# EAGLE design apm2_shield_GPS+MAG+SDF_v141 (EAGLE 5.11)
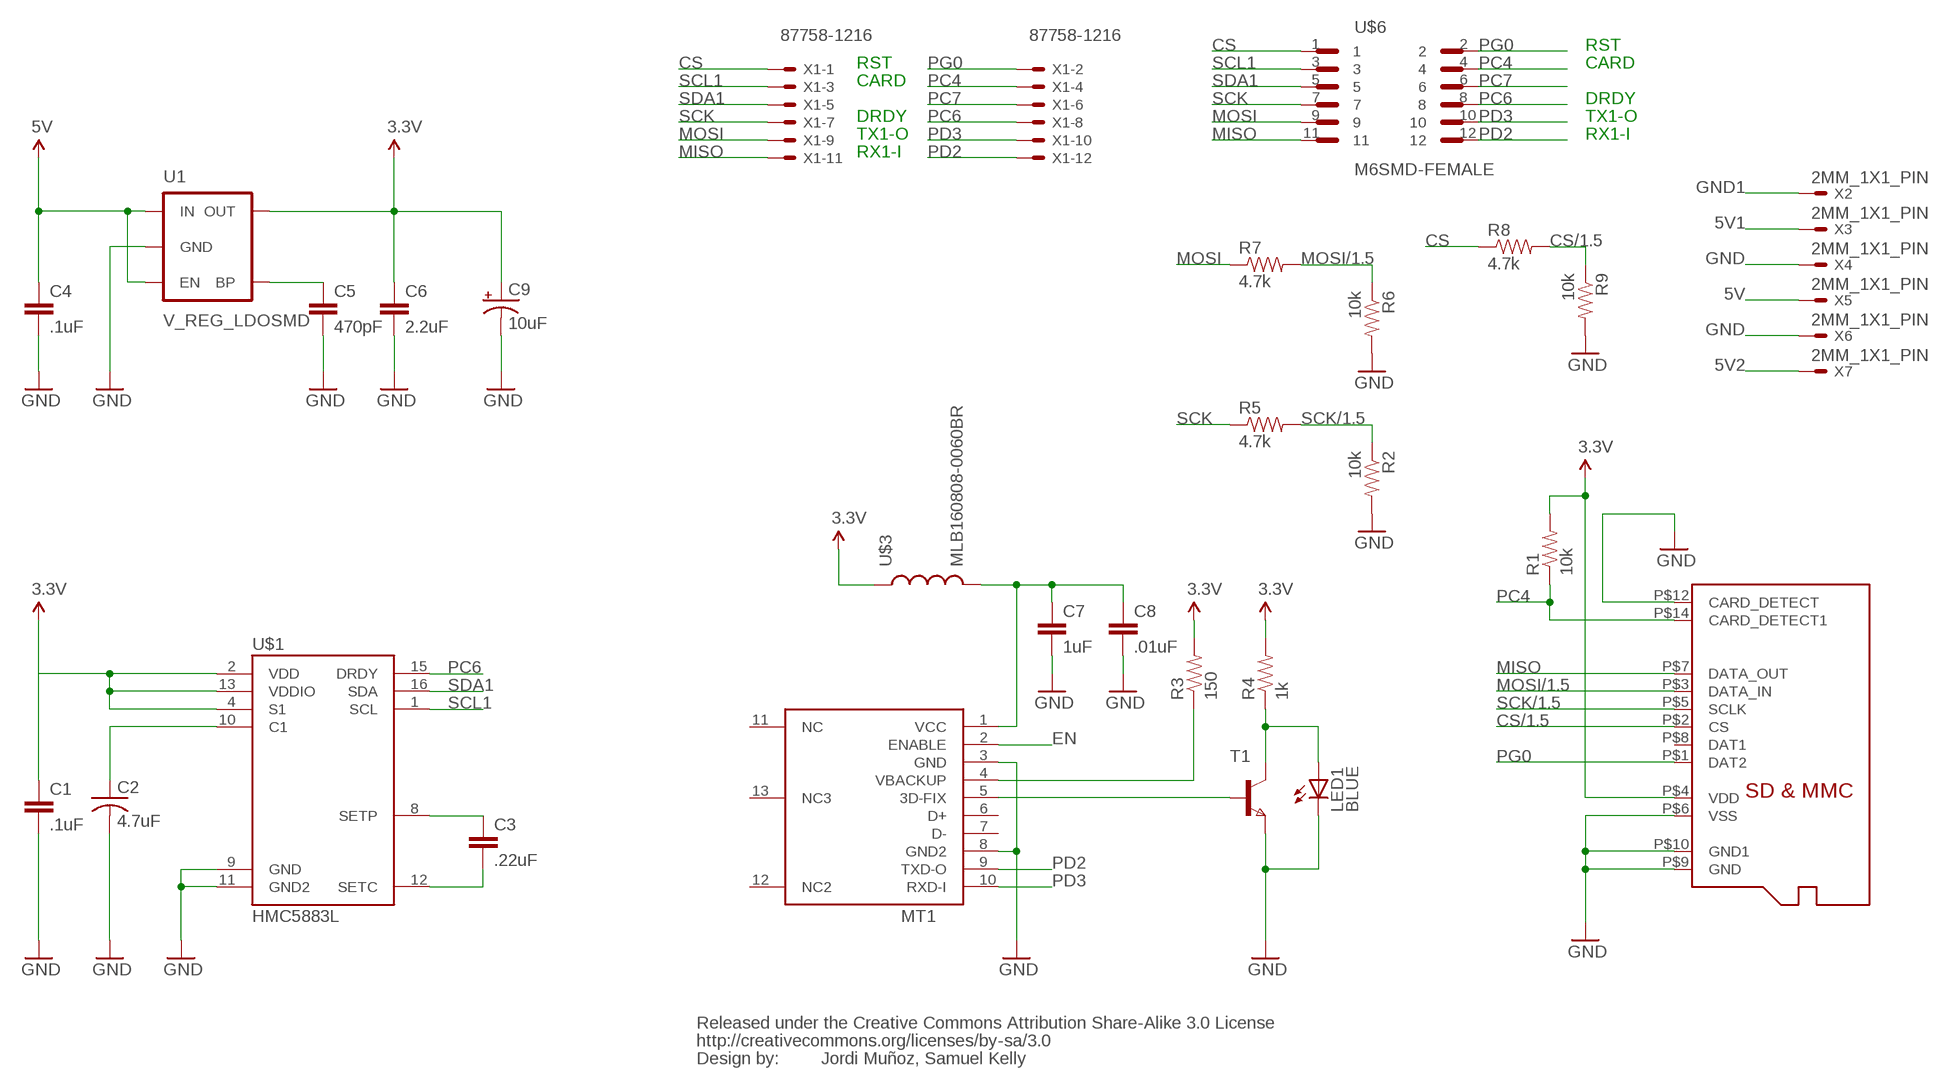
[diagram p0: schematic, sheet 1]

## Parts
C1  .1uF  CAP0402-CAP  [0402-CAP]
C2  4.7uF  C-USC1206  [C1206]
C3  .22uF  CAP0402-CAP  [0402-CAP]
C4  .1uF  CAP0402-CAP  [0402-CAP]
C5  470pF  CAP0402-CAP  [0402-CAP]
C6  2.2uF  CAP0402-CAP  [0402-CAP]
C7  1uF  CAP0402-CAP  [0402-CAP]
C8  .01uF  CAP0402-CAP  [0402-CAP]
C9  10uF  CAP_POL1206  [EIA3216]
LED1  BLUE  LED0603  [LED-0603]
MT1  MEDIATEK_MT3329_ANT_REV  [MEDIATEK_MT3329_ANT_REV]
R1  10k  RESISTOR0402-RES  [0402-RES]
R2  10k  RESISTOR0402-RES  [0402-RES]
R3  150  RESISTOR0402-RES  [0402-RES]
R4  1k  RESISTOR0402-RES  [0402-RES]
R5  4.7k  RESISTOR0402-RES  [0402-RES]
R6  10k  RESISTOR0402-RES  [0402-RES]
R7  4.7k  RESISTOR0402-RES  [0402-RES]
R8  4.7k  RESISTOR0402-RES  [0402-RES]
R9  10k  RESISTOR0402-RES  [0402-RES]
T1  NPNSOT323  [SOT323]
U1  V_REG_LDOSMD  [SOT23-5]
U$1  HMC5883L  [LPCC16]
U$3  MLB160808-0060BR  INDUCTOR0402  [C0402]
U$4  CREATIVE_COMMONS  [CREATIVE_COMMONS]
U$5  MICROSD'NON-PUSH'  [MICROSD_AMPHENOL]
U$6  M6SMD-FEMALE  [M6-2X6-2MM]
X1  87758-1216  [87758-1216]
X2  2MM_1X1_PIN  [2MM_1X1_PIN]
X3  2MM_1X1_PIN  [2MM_1X1_PIN]
X4  2MM_1X1_PIN  [2MM_1X1_PIN]
X5  2MM_1X1_PIN  [2MM_1X1_PIN]
X6  2MM_1X1_PIN  [2MM_1X1_PIN]
X7  2MM_1X1_PIN  [2MM_1X1_PIN]

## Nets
3.3V: C1.1 C6.1 C9.A(+) R1.2 R3.2 R4.2 U1.5(OUT) U$1.2(VDD) U$1.4(S1) U$1.13(VDDIO) U$3.1 U$5.P$4(VDD)
5V: C4.1 U1.1(IN) U1.3(EN) X5.P$1(S)
5V1: X3.P$1(S)
5V2: X7.P$1(S)
CS: R8.1 U$6.1 X1.1
CS/1.5: R8.2 R9.1 U$5.P$2(CS)
EN: MT1.2(ENABLE)
GND: C1.2 C2.2 C4.2 C5.2 C6.2 C7.2 C8.2 C9.C(-) LED1.C MT1.3(GND) MT1.8(GND2) R2.2 R6.2 R9.2 T1.3(E) U1.2(GND) U$1.9(GND) U$1.11(GND2) U$5.P$6(VSS) U$5.P$9(GND) U$5.P$10(GND1) U$5.P$12(CARD_DETECT) X4.P$1(S) X6.P$1(S)
GND1: X2.P$1(S)
MISO: U$5.P$7(DATA_OUT) U$6.11 X1.11
MOSI: R7.1 U$6.9 X1.9
MOSI/1.5: R6.1 R7.2 U$5.P$3(DATA_IN)
N$1: C2.1 U$1.10(C1)
N$2: C3.1 U$1.8(SETP)
N$3: C3.2 U$1.12(SETC)
N$4: C7.1 C8.1 MT1.1(VCC) U$3.2
N$5: C5.1 U1.4(BP)
N$6: MT1.4(VBACKUP) R3.1
N$7: LED1.A R4.1 T1.1(C)
N$8: MT1.5(3D-FIX) T1.2(B)
PC4: R1.1 U$5.P$14(CARD_DETECT1) U$6.4 X1.4
PC6: U$1.15(DRDY) U$6.8 X1.8
PC7: U$6.6 X1.6
PD2: MT1.9(TXD-O) U$6.12 X1.12
PD3: MT1.10(RXD-I) U$6.10 X1.10
PG0: U$5.P$1(DAT2) U$6.2 X1.2
SCK: R5.1 U$6.7 X1.7
SCK/1.5: R2.1 R5.2 U$5.P$5(SCLK)
SCL1: U$1.1(SCL) U$6.3 X1.3
SDA1: U$1.16(SDA) U$6.5 X1.5
Unconnected: MT1.6(D+) MT1.7(D-) MT1.11(NC) MT1.12(NC2) MT1.13(NC3) U$5.P$8(DAT1)

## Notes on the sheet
- RST
- RST | CARD
- CARD
- DRDY
- DRDY | TX1-O
- TX1-O | RX1-I
- RX1-I
- Jordi Muñoz, Samuel Kelly

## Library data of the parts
C1 C3-C8 = SparkFun:CAP: Capacitor
C2 = rcl:C-US: CAPACITOR, American symbol
C9 = SparkFun:CAP_POL: Capacitor Polarized
LED1 = SparkFun:LED: LEDs
MT1 = 3DRobotics:MEDIATEK_MT3329_ANT_REV: Based on MediaTek Single Chip Architecture. Dimension?16mm x 16mm x 6mm. L1 Frequency, C/A code, 66 channels. High Sensitivity?Up to -165dBm tracking, superior urban performances.
R1-R9 = SparkFun:RESISTOR: Resistor
T1 = 3DRobotics:NPNSOT323: NPN TRANSISTOR; DATASHEET: http://www.nxp.com/documents/data_sheet/PDTC143E_SERIES.pdf; LINK: http://www.mouser.com/Search/ProductDetail.aspx?qs=LOCUfHb8d9uiSUZNrng0PQ%3D%3D; MFGPN: PDTC143EU,115
U1 = SparkFun:V_REG_LDO: Voltage Regulator LDO Standard 150mA LDO voltage regulator in SOT-23 layout. Micrel part MIC5205. BP (by-pass) pin is used to lower output noise with 470pF cap.
U$1 = 3DRobotics:HMC5883L: Honeywell HMC5883L 3-axis digital compass IC Successor to the HMC5843.; DATASHEET: http://www.dsscircuits.com/images/datasheets/HMC5883L.pdf; LINK: http://parts.digikey.com/1/parts/2057013-ic-compass-3-axis-i2c-16lcc-smd-hmc5883l-tr.html; MFGPN: HMC5883L-TR
U$3 = SparkFun:INDUCTOR: Inductors
U$4 = SparkFun:CREATIVE_COMMONS
U$5 = 3DRobotics:MICROSD: Micro-SD / Transflash card holder with SPI pinout For the 3M # 2908-05WB-MG and/or 4UCON #19656 push-push type
U$6 = 3DRobotics:M6
X1 = con-molex:87758-1216: 12 Pin - 2mm Dual Row Single Wafer, Vertical T/H HDR Source: http://www.molex.com/pdm_docs/sd/877580616_sd.pdf; MPN: 87758-1216; OC_FARNELL: unknown; OC_NEWARK: 25M5671
X2-X7 = 3DRobotics:2MM_1X1_PIN: 2 Pin - 2mm Dual Row Single Wafer, Vertical T/H HDR

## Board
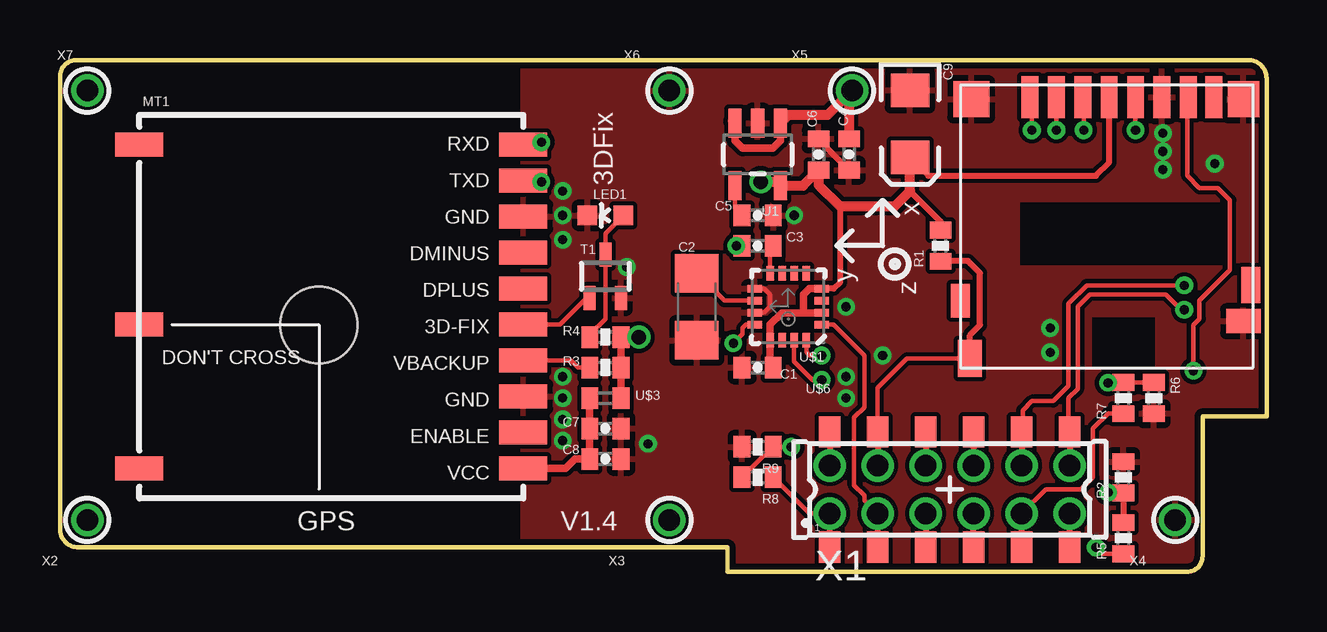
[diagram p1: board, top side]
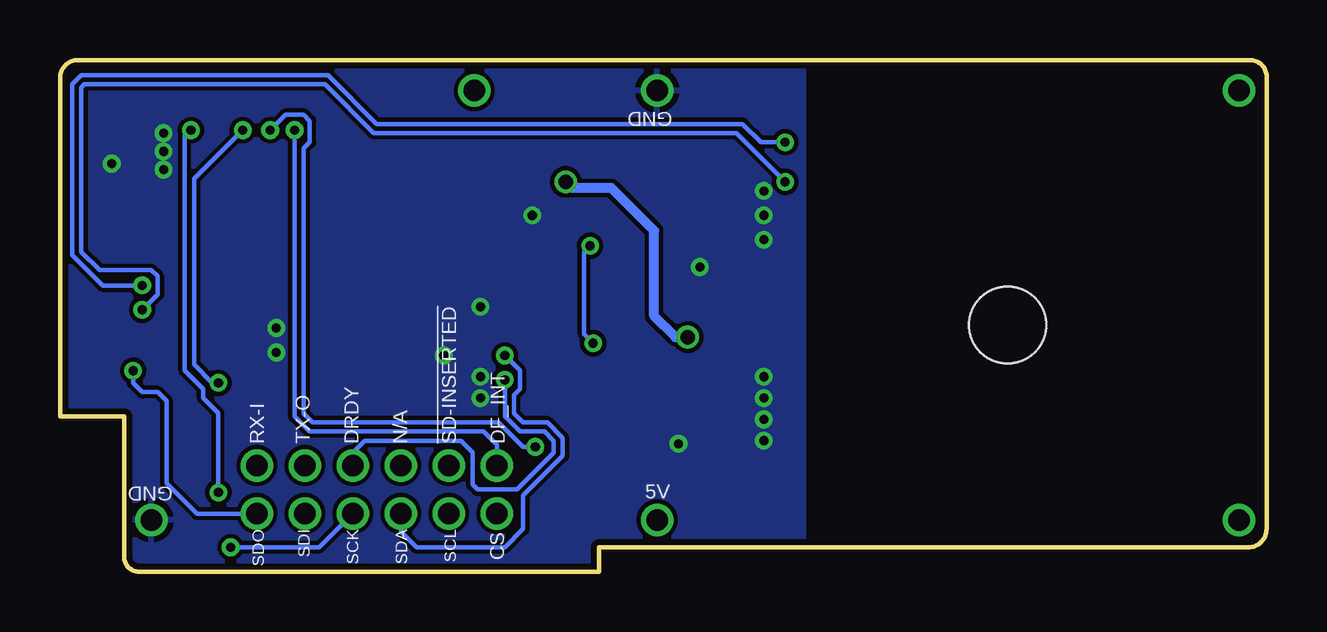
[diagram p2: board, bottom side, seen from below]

Size 50.29 x 21.34 mm. Coordinates in mm from the lower left corner, seen from the top.
Outline: 47.62,0.64 arc-90 46.99,0 27.81,0 27.81,1.02 0.76,1.02 arc-90 0,1.78 0,20.7 arc-90 0.76,21.34 49.53,21.34 arc-90 50.29,20.57 50.29,6.48 47.62,6.48 47.62,0.64
Copper layers (1*2+15*16): Top 0.035mm / dielectric 1.5mm / Route2 0.035mm / dielectric 0.15mm / Route15 0.035mm / dielectric 0.2mm / Bottom 0.035mm
Design rules "3DRobotics_4layers": minimum track width 7mil, minimum drill 15mil, track to track 7mil, track to pad 7mil, pad to pad 7mil, via to via 7mil, smd to smd 0mil, copper to edge 10mil, drill to drill 8mil, minimum pad ring 7mil, minimum via ring 7mil, stop-mask expansion 4mil, vias tented up to drill 25mil, thermal gap 10mil
Holes 3.2 mm at 10.79,10.29

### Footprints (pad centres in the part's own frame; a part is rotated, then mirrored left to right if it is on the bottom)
0402-CAP = smd 0.7 x 0.9: 1 -0.65,0; 2 0.65,0
C1206 = smd 1.6 x 1.8: 1 -1.4,0; 2 1.4,0
EIA3216 = smd 1.4 x 1.6: A 1.4,0; C -1.4,0
LED-0603 = smd 0.8 x 0.8: A 0,-0.75; C 0,0.75
MEDIATEK_MT3329_ANT_REV = smd 2 x 1: 1 -8,6.75; 2 -8,5.25; 3 -8,3.75; 4 -8,2.25; 5 -8,0.75; 6 -8,-0.75; 7 -8,-2.25; 8 -8,-3.75; 9 -8,-5.25; 10 -8,-6.75; 11 8,6.75; 12 8,-6.75; 13 8,0.75
0402-RES = smd 0.7 x 0.9: 1 -0.65,0; 2 0.65,0
SOT323 = smd 0.5 x 1: 1 0,0.9; 2 -0.65,-0.9; 3 0.65,-0.9
SOT23-5 = smd 0.55 x 1.2: 1 -0.95,-1.3; 2 0,-1.3; 3 0.95,-1.3; 4 0.95,1.3; 5 -0.95,1.3
LPCC16 = smd 0.6 x 0.3: 1 -1.4,0.75; 2 -1.4,0.25; 3 -1.4,-0.25; 4 -1.4,-0.75; 9 1.4,-0.75; 10 1.4,-0.25; 11 1.4,0.25; 12 1.4,0.75 | smd 0.3 x 0.6: 5 -0.75,-1.4; 6 -0.25,-1.4; 7 0.25,-1.4; 8 0.75,-1.4; 13 0.75,1.4; 14 0.25,1.4; 15 -0.25,1.4; 16 -0.75,1.4
C0402 = smd 0.7 x 0.9: 1 -0.65,0; 2 0.65,0
MICROSD_AMPHENOL = smd 0.7 x 1.75: P$1 7.7,-1; P$2 6.6,-1; P$3 5.5,-1; P$4 4.4,-1; P$5 3.3,-1; P$6 2.2,-1; P$7 1.1,-1; P$8 0.04,-1 | smd 1.5 x 1.5: P$9 10.15,-0.9 | smd 1.3 x 1.5: P$10 -1.2,-0.9 | smd 0.8 x 1.5: P$11 -1.5,6.85 | smd 1.45 x 1: P$12 -1.2,8.35 | smd 0.8 x 1.4: P$13 10.6,7.5 | smd 1 x 1.55: P$14 10.2,9.9
M6-2X6-2MM = smd 0.89 x 1.3: 1 -5,-2.4; 2 -5,2.4; 3 -3,-2.4; 4 -3,2.4; 5 -1,-2.4; 6 -1,2.4; 7 1,-2.4; 8 1,2.4; 9 3,-2.4; 10 3,2.4; 11 5,-2.4; 12 5,2.4
87758-1216 = drill 0.9 pad 1.27 round: 1 -5,-1; 2 -5,1; 3 -3,-1; 4 -3,1; 5 -1,-1; 6 -1,1; 7 1,-1; 8 1,1; 9 3,-1; 10 3,1; 11 5,-1; 12 5,1
2MM_1X1_PIN = drill 0.9 pad 1.27 round: P$1 0,0

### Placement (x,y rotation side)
C1  29.08,8.51 180 top
C2  26.54,11.05 270 top
C3  29.08,13.59 180 top
C4  32.89,17.4 270 top
C5  29.08,14.86 0 top
C6  31.62,17.4 90 top
C7  22.73,5.97 0 top
C8  22.73,4.7 0 top
C9  35.43,18.67 270 top
LED1  22.73,14.86 90 top
MT1  11.3,11.05 180 top
R1  36.7,13.59 90 top
R2  44.32,3.94 90 top
R3  22.73,8.51 0 top
R4  22.73,9.78 0 top
R5  44.32,1.4 90 top
R6  45.59,7.24 270 top
R7  44.32,7.24 90 top
R8  29.08,3.94 180 top
R9  29.08,5.21 180 top
T1  22.73,12.32 0 top
U1  29.08,17.4 180 top
U$1  30.35,11.05 180 top
U$3  22.73,7.24 180 top
U$4  not placed on the board
U$5  48.13,18.8 180 top
U$6  37.08,3.43 0 top
X1  37.08,3.43 0 top
X2  1.14,2.16 0 top
X3  25.4,2.16 0 top
X4  46.48,2.16 0 top
X5  33.02,20.07 0 top
X6  25.4,20.07 0 top
X7  1.14,20.07 0 top

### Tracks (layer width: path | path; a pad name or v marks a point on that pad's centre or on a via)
3.3V  (via drill 0.6)
  Top 0.178: 29.72,8.51 C1.1
  Top 0.254: U$5.P$4 43.73,17.06 43.18,16.51 36.19,16.51 C9.A | U$1.4 32.25,11.8 32.51,12.06 32.51,15.24 | R1.2 36.7,14.6 35.43,15.88
  Top 0.305: U$3.1 R3.2 R4.2 | 30.99,10.79 30.1,10.79 29.6,10.3 U$1.13 29.6,8.62 29.72,8.51 | 30.99,10.79 U$1.2 | U$1.4 31.23,11.8 30.99,11.56 30.99,10.79 | 31.62,16.76 31.61,16.76 C6.1
  Top 0.406: C9.A 35.43,15.88 34.8,15.24 32.51,15.24 31.62,16.13 C6.1 30.97,16.1 U1.5 29.88,16.26 v29.21,16.26 | R4.2 v24.13,9.78
  Bottom 0.406: v24.13,9.78 24.64,9.78 25.53,10.67 25.53,14.22 27.3,16 28.96,16 v29.21,16.26
5V
  Top 0.305: U1.3 28.13,17.97 28.45,17.65 29.72,17.65 30.03,17.97 U1.1
  Top 0.406: U1.3 28.04,18.8 | 32.89,18.41 C4.1 32.89,19.94 X5.P$1 32,19.05 30.38,19.05 U1.1
CS
  Top 0.178: X1.1 31.24,2.43 R8.1
  Top 0.254: U$6.1 X1.1
CS/1.5  (via drill 0.38)
  Top 0.178: U$5.P$2 v41.53,18.42 v41.53,18.41 | v30.48,5.21 R9.1 29.7,5.21 R8.2
  Bottom 0.178: v41.53,18.41 40.89,19.05 40.13,19.05 39.88,18.8 39.88,17.91 40.13,17.65 40.13,6.6 39.75,6.22 32,6.22 30.99,5.21 v30.48,5.21
GND  (via drill 0.38)
  Top 0.178: U$1.9 29.35,11.8 29.59,11.56 29.59,11.05 29.34,10.8 U$1.11
  Top 0.203: C4.2 32.89,16.78
  Top 0.254: C6.2 31.62,18.02 C4.2
  other vias: 20.96,7.24 20.96,14.86 20.96,13.84 20.96,15.88 48.13,17.02 45.97,16.76 41.27,10.16 24.51,5.33 20.96,8.13 20.96,6.35 30.61,14.86 23.62,12.7 41.27,9.14 20.96,5.46 32.77,7.24 32.77,8.13 45.97,18.29 45.97,17.53 32.77,11.05 34.29,9.02
  pour Bottom: 19.3,0.89 19.3,23.75 50.67,23.75 50.67,-2.92 27.81,-2.92 27.81,0.89
  pour Top: 19.3,0.89 19.3,23.75 50.67,23.75 50.67,-2.92 27.81,-2.92 27.81,0.89
MISO  (via drill 0.38)
  Top 0.178: U$5.P$7 46.99,19.75 46.99,16.51 47.5,16 48.26,16 48.77,15.49 48.77,12.57 47.5,11.3 47.5,10.54 47.24,10.29 v47.24,8.38
  Top 0.254: U$6.11 X1.11
  Bottom 0.178: v47.24,8.38 47.24,7.87 46.86,7.49 46.23,7.49 45.85,7.11 45.85,3.68 44.58,2.41 42.1,2.41 X1.11
MOSI
  Top 0.178: X1.9 41.08,3.43 42.54,3.43 43.05,3.94 43.05,5.97 43.69,6.6 44.31,6.6 R7.1
  Top 0.254: U$6.9 X1.9
MOSI/1.5  (via drill 0.38)
  Top 0.178: v42.67,18.41 42.67,19.76 U$5.P$3 | R6.1 R7.2 43.7,7.89 v43.69,7.87
  Bottom 0.178: v42.67,18.41 44.7,16.38 44.7,8.64 43.94,7.87 v43.69,7.87
N$1
  Top 0.178: U$1.10 27.69,11.3 C2.1
N$2
  Top 0.178: C3.1 29.73,13.48 29.59,13.33 29.59,12.46 U$1.8
N$3  (via drill 0.38)
  Top 0.178: v28.19,13.59 C3.2 | U$1.12 28.59,10.3 28.45,10.16 28.45,9.91 v28.07,9.52
  Bottom 0.178: v28.19,13.59 28.45,13.33 28.45,9.91 v28.07,9.52
N$4
  Top 0.305: U$3.2 C7.1 C8.1 21.46,4.7 21.06,4.3 MT1.1
N$5
  Top 0.178: U1.4 28.13,15.16 C5.1
N$6
  Top 0.178: MT1.4 21.3,8.8 21.59,8.51 R3.1
N$7
  Top 0.178: R4.1 22.08,9.89 22.73,10.54 T1.1 22.73,14.11 LED1.A
N$8
  Top 0.178: MT1.5 20.84,10.3 21.97,11.43 22.07,11.43 T1.2
PC4
  Top 0.178: U$5.P$14 35.31,8.89 34.08,7.67 U$6.4
  Top 0.254: U$5.P$14 37.93,9.87 38.35,10.29 38.35,12.45 37.85,12.95 36.72,12.95 R1.1 | U$6.4 X1.4
PC6  (via drill 0.38)
  Top 0.178: U$1.15 30.6,8.77 31.37,8 v31.75,8
  Top 0.254: U$6.8 X1.8
  Bottom 0.178: X1.8 38.08,4.97 37.59,5.46 33.58,5.46 33.1,4.98 33.1,3.63 32.89,3.43 31.24,3.43 29.72,4.95 29.72,5.46 30.1,5.84 31.12,5.84 31.75,6.48 v31.75,8
PC7
  Top 0.254: U$6.6 X1.6
PD2  (via drill 0.38)
  Top 0.178: v20.07,16.26 19.35,16.26 MT1.9 | v46.86,10.92 46.74,10.92 46.1,11.56 42.93,11.56 42.42,11.05 42.42,7.62 42.04,7.24 42.04,5.88 U$6.12
  Top 0.254: U$6.12 X1.12
  Bottom 0.178: v20.07,16.26 22.1,18.29 37.21,18.29 39.24,20.32 49.28,20.32 49.4,20.19 49.4,13.33 48.64,12.57 46.48,12.57 46.23,12.32 46.23,11.56 v46.86,10.92
PD3  (via drill 0.38)
  Top 0.178: v20.07,17.91 19.41,17.91 MT1.10 | v46.86,11.94 42.8,11.94 42.04,11.18 42.04,7.75 41.4,7.11 40.51,7.11 40.13,6.73 40.13,5.88 U$6.10
  Top 0.254: U$6.10 X1.10
  Bottom 0.178: v20.07,17.91 21.08,17.91 21.84,18.67 37.08,18.67 39.12,20.7 49.4,20.7 49.78,20.32 49.78,13.21 48.51,11.94 v46.86,11.94
PG0  (via drill 0.38)
  Top 0.178: v40.51,18.41 40.51,19.72 U$5.P$1
  Top 0.254: U$6.2 X1.2
  Bottom 0.178: v40.51,18.41 40.51,6.48 39.88,5.84 32.64,5.84 32.08,5.29 X1.2
SCK  (via drill 0.38)
  Top 0.178: R5.1 43.45,0.75 v43.18,1.02
  Top 0.254: X1.7 U$6.7
  Bottom 0.178: v43.18,1.02 39.5,1.02 X1.7
SCK/1.5  (via drill 0.38)
  Top 0.178: v44.83,18.41 U$5.P$5 | v43.69,3.3 44.31,3.3 R2.1
  Top 0.254: R2.1 R5.2
  Bottom 0.178: v44.83,18.41 45.09,18.16 45.09,8.38 44.32,7.62 44.32,7.24 43.7,6.62 43.7,3.32 v43.69,3.3
SCL1
  Top 0.178: U$1.1 32.25,10.3 33.53,9.02 33.53,6.86 33.1,6.43 33.1,3.61 33.53,3.17 33.53,2.98 X1.3
  Top 0.254: U$6.3 X1.3
SDA1  (via drill 0.38)
  Top 0.178: U$6.5 36.07,1.01 | U$1.16 31.11,9.15 31.24,9.02 v31.75,9.02
  Top 0.254: U$6.5 X1.5
  Bottom 0.178: X1.5 36.08,1.67 35.43,1.02 31.75,1.02 30.99,1.78 30.99,3.17 29.34,4.83 29.34,5.59 29.97,6.22 30.99,6.22 31.37,6.6 31.37,7.37 31.12,7.62 31.12,8.38 v31.75,9.02

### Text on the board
tPlace: 3DFix | x | y | z | GPS | V1.4
bPlace: GND | DF_INT | !SD-INSERTED | N/A | DRDY | TX-O | RX-I | GND | 5V | CS | SCL | SDA | SCK | SDI | SDO
Document: DataFlash inserted | Jordi Muñoz, Samuel Kelly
